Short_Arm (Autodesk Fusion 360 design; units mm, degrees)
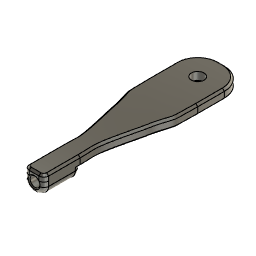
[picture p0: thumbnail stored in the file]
base_feature "Base Feature" bodies "Tube arm"
chamfer "Chamfer1" distance 0.8
named bodies: "Tube arm"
